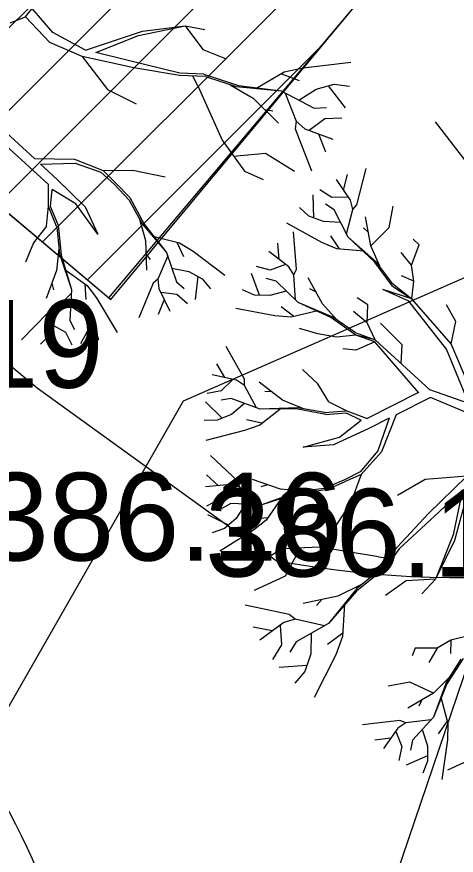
# Model space of a CAD drawing. Extents: x -438233 to -437334, y -1133133 to -1132623.
# Drawn here: x -438141.5 to -438137.75, y -1132967.72 to -1132960.55 of the extents above; entities that cross this region are included whole.
import ezdxf

# ---------------------------------------------------------------- set-up
doc = ezdxf.new("R2010")
doc.units = 0
for name, color, linetype in [('Vrstva 1', 7, 'Continuous'), ('Vrstva 11', 7, 'Continuous'), ('Vrstva 3', 7, 'Continuous'), ('Vrstva 40', 7, 'Continuous'), ('Vrstva 53', 7, 'Continuous')]:
    doc.layers.add(name, color=color, linetype=linetype)

msp = doc.modelspace()

# ---------------------------------------------------------------- linework, layer by layer
at = {"layer": 'Vrstva 1'}
for p, q in [((-438141.4293, -1132960.546), (-438141.3741, -1132960.4752)), ((-438141.1972, -1132960.6792), (-438141.3741, -1132960.4752)), ((-438141.5613, -1132960.5982), (-438141.4293, -1132960.546)), ((-438141.2218, -1132960.7661), (-438141.4293, -1132960.546)), ((-438140.4655, -1132960.7055), (-438140.0649, -1132960.6234)), ((-438140.4295, -1132960.669), (-438140.0649, -1132960.6234)), ((-438140.0649, -1132960.6234), (-438139.9149, -1132960.8255)), ((-438140.0649, -1132960.6234), (-438139.8963, -1132960.654)), ((-438140.9165, -1132960.8303), (-438141.1972, -1132960.6792)), ((-438140.9165, -1132960.8303), (-438140.4295, -1132960.669)), ((-438140.8302, -1132960.8519), (-438140.4655, -1132960.7055)), ((-438140.9459, -1132960.8855), (-438141.2218, -1132960.7661)), ((-438140.5633, -1132960.9167), (-438140.8302, -1132960.8519)), ((-438139.9149, -1132960.8255), (-438139.7146, -1132960.9059)), ((-438140.9459, -1132960.8855), (-438140.7282, -1132961.1668)), ((-438140.5033, -1132960.9832), (-438140.9459, -1132960.8855)), ((-438140.1122, -1132961.0264), (-438140.5633, -1132960.9167)), ((-438139.0567, -1132960.9814), (-438138.65, -1132960.9335)), ((-438140.1134, -1132961.0474), (-438140.5033, -1132960.9832)), ((-438139.9065, -1132961.0354), (-438140.1122, -1132961.0264)), ((-438139.4615, -1132961.1584), (-438139.2186, -1132961.0174)), ((-438139.2186, -1132961.0174), (-438139.0567, -1132960.9814)), ((-438139.8927, -1132961.057), (-438140.1134, -1132961.0474)), ((-438139.9575, -1132961.1368), (-438140.0001, -1132961.0522)), ((-438139.9065, -1132961.0354), (-438139.6102, -1132961.132)), ((-438139.8927, -1132961.057), (-438139.63, -1132961.1428)), ((-438139.2438, -1132961.0318), (-438139.0909, -1132961.0894)), ((-438140.7282, -1132961.1668), (-438140.4829, -1132961.2885)), ((-438139.9575, -1132961.1368), (-438139.7506, -1132961.6016)), ((-438139.6798, -1132961.1266), (-438139.4855, -1132961.2411)), ((-438139.63, -1132961.1428), (-438139.2444, -1132961.18)), ((-438139.6102, -1132961.132), (-438139.2444, -1132961.18)), ((-438139.0939, -1132961.2573), (-438138.9451, -1132961.1638)), ((-438138.9451, -1132961.1638), (-438138.7928, -1132961.1224)), ((-438138.845, -1132961.1368), (-438138.6998, -1132961.3251)), ((-438138.7928, -1132961.1224), (-438138.662, -1132961.1386)), ((-438139.4855, -1132961.2411), (-438139.2684, -1132961.4546)), ((-438139.2444, -1132961.18), (-438138.9631, -1132961.3257)), ((-438139.2108, -1132961.1974), (-438139.1184, -1132961.4391)), ((-438139.3859, -1132961.3389), (-438139.3164, -1132961.3503)), ((-438138.9631, -1132961.3257), (-438138.8593, -1132961.3221)), ((-438139.1184, -1132961.4391), (-438139.1262, -1132961.5044)), ((-438139.1184, -1132961.4391), (-438139.0441, -1132961.5038)), ((-438139.0057, -1132961.5158), (-438138.8725, -1132961.4157)), ((-438138.8725, -1132961.4157), (-438138.7262, -1132961.4097)), ((-438137.6767, -1132961.7678), (-438137.928, -1132961.444)), ((-438139.1262, -1132961.5044), (-438138.9847, -1132961.8619)), ((-438139.0441, -1132961.5038), (-438138.8036, -1132961.592)), ((-438141.5925, -1132961.5374), (-438141.3525, -1132961.7587)), ((-438138.9271, -1132961.547), (-438138.8659, -1132961.7)), ((-438141.5961, -1132961.6484), (-438141.2326, -1132961.9794)), ((-438139.7506, -1132961.6016), (-438139.5599, -1132961.8655)), ((-438139.6528, -1132961.7371), (-438139.3805, -1132961.7125)), ((-438139.3805, -1132961.7125), (-438139.1316, -1132961.8667)), ((-438141.3525, -1132961.7587), (-438141.0101, -1132961.7635)), ((-438141.3028, -1132961.8049), (-438141.0059, -1132961.7977)), ((-438141.3028, -1132961.8049), (-438141.1588, -1132961.9375)), ((-438141.0101, -1132961.7635), (-438140.7672, -1132961.8595)), ((-438141.0059, -1132961.7977), (-438140.7858, -1132961.8745)), ((-438140.7858, -1132961.8745), (-438140.67, -1132961.9794)), ((-438140.7672, -1132961.8595), (-438140.5129, -1132961.8565)), ((-438140.7672, -1132961.8595), (-438140.6574, -1132961.9674)), ((-438140.5129, -1132961.8565), (-438140.237, -1132961.9153)), ((-438139.5599, -1132961.8655), (-438139.3985, -1132961.9363)), ((-438138.5974, -1132962.1535), (-438138.52, -1132961.8428)), ((-438141.1588, -1132961.9375), (-438140.9213, -1132962.1708)), ((-438138.6531, -1132962.1145), (-438138.7737, -1132961.9382)), ((-438138.7113, -1132962.0287), (-438138.6789, -1132961.895)), ((-438141.232, -1132962.1642), (-438141.2326, -1132961.9794)), ((-438141.2152, -1132962.1666), (-438141.2032, -1132962.0238)), ((-438141.0011, -1132962.1444), (-438141.2032, -1132962.0238)), ((-438140.5429, -1132962.1126), (-438140.67, -1132961.9794)), ((-438140.6574, -1132961.9674), (-438140.5387, -1132962.0916)), ((-438138.8121, -1132962.0911), (-438138.9146, -1132962.0245)), ((-438140.5387, -1132962.0916), (-438140.4163, -1132962.3201)), ((-438138.965, -1132962.2668), (-438138.9728, -1132962.0689)), ((-438138.6735, -1132962.0875), (-438138.8121, -1132962.0911)), ((-438141.2494, -1132962.3357), (-438141.232, -1132962.1642)), ((-438141.163, -1132962.3435), (-438141.2314, -1132962.1732)), ((-438141.1516, -1132962.3261), (-438141.2152, -1132962.1666)), ((-438140.811, -1132962.4035), (-438141.0011, -1132962.1444)), ((-438140.9213, -1132962.1708), (-438140.811, -1132962.4035)), ((-438140.5429, -1132962.1126), (-438140.4343, -1132962.3153)), ((-438138.7935, -1132962.1955), (-438138.866, -1132962.1481)), ((-438138.6339, -1132962.1943), (-438138.6531, -1132962.1145)), ((-438138.6339, -1132962.1943), (-438138.5974, -1132962.1535)), ((-438138.3227, -1132962.3484), (-438138.2879, -1132962.1649)), ((-438139.0076, -1132962.2513), (-438139.0886, -1132962.1769)), ((-438138.6735, -1132962.4306), (-438138.7935, -1132962.1955)), ((-438138.6879, -1132962.4024), (-438138.6339, -1132962.1943)), ((-438140.4547, -1132962.2769), (-438140.4043, -1132962.4586)), ((-438140.4343, -1132962.3153), (-438140.2238, -1132962.5606)), ((-438138.8972, -1132962.475), (-438139.1959, -1132962.3106)), ((-438138.884, -1132962.2968), (-438139.0076, -1132962.2513)), ((-438138.7383, -1132962.3052), (-438138.884, -1132962.2968)), ((-438138.4798, -1132962.5055), (-438138.5236, -1132962.256)), ((-438141.2494, -1132962.3357), (-438141.3609, -1132962.4784)), ((-438141.163, -1132962.3435), (-438141.139, -1132962.5726)), ((-438141.1516, -1132962.3261), (-438141.124, -1132962.5846)), ((-438140.4163, -1132962.3201), (-438140.2238, -1132962.5606)), ((-438139.1155, -1132962.7029), (-438139.1401, -1132962.3838)), ((-438138.5002, -1132962.3916), (-438138.5422, -1132962.3502)), ((-438138.4798, -1132962.5055), (-438138.3227, -1132962.3484)), ((-438140.4043, -1132962.4586), (-438140.3971, -1132962.7123)), ((-438140.3426, -1132962.4227), (-438140.1146, -1132962.4778)), ((-438138.7455, -1132962.5313), (-438138.8211, -1132962.418)), ((-438138.448, -1132962.6399), (-438138.6735, -1132962.4306)), ((-438138.4294, -1132962.6429), (-438138.6735, -1132962.4306)), ((-438138.0648, -1132962.4948), (-438138.1181, -1132962.448)), ((-438141.3609, -1132962.4784), (-438141.4311, -1132962.6452)), ((-438141.1438, -1132962.5294), (-438141.1648, -1132962.7165)), ((-438140.138, -1132962.4718), (-438140.0793, -1132962.5954)), ((-438140.1146, -1132962.4778), (-438139.9965, -1132962.5498)), ((-438139.2637, -1132962.6207), (-438139.2751, -1132962.4828)), ((-438138.7695, -1132962.5289), (-438138.8972, -1132962.475)), ((-438138.5362, -1132962.5499), (-438138.7695, -1132962.5289)), ((-438138.4036, -1132962.6771), (-438138.4798, -1132962.5055)), ((-438138.1313, -1132962.6705), (-438138.0648, -1132962.4948)), ((-438141.139, -1132962.5726), (-438141.0359, -1132962.8791)), ((-438141.124, -1132962.5846), (-438141.0359, -1132962.8791)), ((-438140.4007, -1132962.5744), (-438140.3653, -1132962.6218)), ((-438140.2136, -1132962.5906), (-438140.2982, -1132962.7891)), ((-438140.2238, -1132962.5606), (-438140.1392, -1132962.8113)), ((-438139.9965, -1132962.5498), (-438139.7254, -1132962.7561)), ((-438139.1809, -1132962.6831), (-438139.3507, -1132962.5541)), ((-438138.1313, -1132962.6705), (-438138.2213, -1132962.5607)), ((-438139.2079, -1132962.6645), (-438139.3387, -1132962.7113)), ((-438138.2939, -1132962.8492), (-438138.448, -1132962.6399)), ((-438138.2927, -1132962.8276), (-438138.4294, -1132962.6429)), ((-438138.111, -1132962.806), (-438138.1313, -1132962.6705)), ((-438141.1648, -1132962.7165), (-438141.253, -1132962.954)), ((-438141.0941, -1132962.7063), (-438140.9033, -1132962.8431)), ((-438140.1788, -1132962.695), (-438140.0349, -1132962.7237)), ((-438140.0349, -1132962.7237), (-438139.9203, -1132962.7867)), ((-438139.4292, -1132962.9272), (-438139.4988, -1132962.7419)), ((-438139.3387, -1132962.7113), (-438139.4568, -1132962.6807)), ((-438139.1371, -1132962.7532), (-438139.1809, -1132962.6831)), ((-438139.1371, -1132962.7532), (-438139.1155, -1132962.7029)), ((-438140.2982, -1132962.7891), (-438140.3402, -1132962.8239)), ((-438140.2982, -1132962.7891), (-438140.291, -1132962.8707)), ((-438140.1392, -1132962.8113), (-438140.0751, -1132962.8689)), ((-438139.9587, -1132962.7657), (-438139.9803, -1132962.963)), ((-438139.9203, -1132962.7867), (-438139.8502, -1132962.8725)), ((-438139.2889, -1132962.8054), (-438139.3722, -1132962.7826)), ((-438139.1, -1132962.9902), (-438139.2889, -1132962.8054)), ((-438139.1227, -1132962.9686), (-438139.1371, -1132962.7532)), ((-438138.893, -1132963.001), (-438139.0136, -1132962.7772)), ((-438138.111, -1132962.806), (-438138.2165, -1132962.761)), ((-438138.1283, -1132962.9578), (-438138.111, -1132962.806)), ((-438141.205, -1132962.8251), (-438141.1894, -1132962.8821)), ((-438141.0359, -1132962.8791), (-438141.0509, -1132963.1424)), ((-438140.9231, -1132962.8293), (-438140.9147, -1132962.9648)), ((-438140.9033, -1132962.8431), (-438140.8206, -1132962.954)), ((-438140.3402, -1132962.8239), (-438140.4613, -1132963.1202)), ((-438140.291, -1132962.8707), (-438140.1974, -1132963.0626)), ((-438139.4736, -1132962.9254), (-438139.5744, -1132962.8804)), ((-438139.2019, -1132962.8912), (-438139.3429, -1132962.9302)), ((-438138.9482, -1132962.8984), (-438139.0016, -1132962.872)), ((-438138.1547, -1132962.977), (-438138.3754, -1132962.8792)), ((-438138.1283, -1132962.9578), (-438138.3754, -1132962.8792)), ((-438138.2939, -1132962.8492), (-438138.1283, -1132962.9578)), ((-438138.2927, -1132962.8276), (-438138.2927, -1132962.8276)), ((-438138.2927, -1132962.8276), (-438138.1283, -1132962.9578)), ((-438141.0371, -1132962.9103), (-438141.1894, -1132963.0626)), ((-438140.8206, -1132962.954), (-438140.646, -1132963.2467)), ((-438140.2742, -1132962.9007), (-438140.1362, -1132962.9175)), ((-438140.1362, -1132962.9175), (-438140.0451, -1132962.9978)), ((-438139.3429, -1132962.9302), (-438139.4736, -1132962.9254)), ((-438138.5056, -1132963.0081), (-438138.595, -1132962.9488)), ((-438137.7937, -1132963.3422), (-438138.1283, -1132962.9578)), ((-438141.0437, -1132963.02), (-438140.9213, -1132963.101)), ((-438140.2448, -1132962.9642), (-438140.297, -1132963.0926)), ((-438139.1371, -1132963.1083), (-438139.2451, -1132963.0249)), ((-438138.8205, -1132963.1185), (-438139.1, -1132962.9902)), ((-438138.8025, -1132963.1149), (-438139.1, -1132962.9902)), ((-438138.7665, -1132963.1395), (-438138.893, -1132963.001)), ((-438138.5116, -1132963.1641), (-438138.5056, -1132963.0081)), ((-438137.8315, -1132963.389), (-438138.1547, -1132962.977)), ((-438137.7535, -1132963.1521), (-438137.8327, -1132963.0099)), ((-438141.2422, -1132963.08), (-438141.4653, -1132963.3085)), ((-438141.1894, -1132963.0626), (-438141.2422, -1132963.08)), ((-438141.1894, -1132963.0626), (-438141.214, -1132963.1412)), ((-438140.9213, -1132963.101), (-438140.8386, -1132963.2023)), ((-438139.2991, -1132963.1029), (-438139.6337, -1132963.0411)), ((-438139.1605, -1132963.1137), (-438139.2991, -1132963.1029)), ((-438138.9326, -1132963.0609), (-438139.1605, -1132963.1137)), ((-438138.5116, -1132963.1641), (-438138.6267, -1132963.0675)), ((-438141.214, -1132963.1412), (-438141.199, -1132963.3541)), ((-438141.2098, -1132963.1748), (-438141.0881, -1132963.2419)), ((-438141.0509, -1132963.1424), (-438141.0125, -1132963.2203)), ((-438140.8667, -1132963.1682), (-438140.9603, -1132963.3427)), ((-438138.6082, -1132963.2672), (-438138.8205, -1132963.1185)), ((-438138.6135, -1132963.2469), (-438138.8025, -1132963.1149)), ((-438138.4408, -1132963.3086), (-438138.5116, -1132963.1641)), ((-438138.2123, -1132963.3512), (-438138.3976, -1132963.1647)), ((-438137.7937, -1132963.3422), (-438137.7535, -1132963.1521)), ((-438141.2062, -1132963.2455), (-438141.3022, -1132963.3445)), ((-438141.0881, -1132963.2419), (-438141.0335, -1132963.3517)), ((-438140.8386, -1132963.2023), (-438140.8062, -1132963.3079)), ((-438138.9332, -1132963.2564), (-438139.0874, -1132963.2121)), ((-438138.6135, -1132963.2469), (-438138.4408, -1132963.3086)), ((-438138.7737, -1132963.2852), (-438138.9332, -1132963.2564)), ((-438138.6082, -1132963.2672), (-438138.7737, -1132963.2852)), ((-438138.4408, -1132963.3086), (-438138.6082, -1132963.2672)), ((-438138.4462, -1132963.3248), (-438138.6082, -1132963.2672)), ((-438137.9754, -1132963.7351), (-438138.4408, -1132963.3086)), ((-438139.5588, -1132963.6451), (-438139.7141, -1132963.3656)), ((-438138.6082, -1132963.3956), (-438138.7185, -1132963.3848)), ((-438138.4462, -1132963.3248), (-438138.6082, -1132963.3956)), ((-438138.0696, -1132963.7608), (-438138.4462, -1132963.3248)), ((-438138.2201, -1132963.5101), (-438138.2123, -1132963.3512)), ((-438137.6407, -1132963.8532), (-438137.8315, -1132963.389)), ((-438137.567, -1132963.879), (-438137.7937, -1132963.3422)), ((-438139.7273, -1132963.6319), (-438139.7951, -1132963.5125)), ((-438139.6259, -1132963.6547), (-438139.8341, -1132963.6079)), ((-438138.9314, -1132963.6853), (-438139.0622, -1132963.5611)), ((-438139.6595, -1132963.6487), (-438139.7579, -1132963.7459)), ((-438139.5576, -1132963.7003), (-438139.6259, -1132963.6547)), ((-438139.5576, -1132963.7003), (-438139.5588, -1132963.6451)), ((-438139.2325, -1132963.8232), (-438139.4346, -1132963.6703)), ((-438141.329, -1132963.718), (-438141.329, -1132963.718)), ((-438139.7579, -1132963.7459), (-438139.8784, -1132963.7674)), ((-438139.455, -1132963.8898), (-438139.5576, -1132963.7003)), ((-438139.3255, -1132963.753), (-438139.3842, -1132963.7518)), ((-438138.8367, -1132963.8394), (-438138.9314, -1132963.6853)), ((-438137.6407, -1132963.8532), (-438137.9754, -1132963.7351)), ((-438139.6733, -1132963.8106), (-438139.7585, -1132963.825)), ((-438139.425, -1132963.9006), (-438139.6733, -1132963.8106)), ((-438139.0592, -1132963.897), (-438139.2325, -1132963.8232)), ((-438138.0714, -1132963.7596), (-438138.5098, -1132963.9822)), ((-438137.9688, -1132963.8022), (-438138.2615, -1132963.9486)), ((-438137.1022, -1132964.1645), (-438137.9688, -1132963.8022)), ((-438139.7501, -1132963.9798), (-438139.891, -1132963.84)), ((-438139.5582, -1132963.8526), (-438139.6703, -1132963.9462)), ((-438139.2433, -1132963.894), (-438139.4286, -1132964.0373)), ((-438139.1024, -1132963.8892), (-438139.425, -1132963.9006)), ((-438138.8756, -1132963.9306), (-438139.1024, -1132963.8892)), ((-438138.8367, -1132963.8394), (-438138.6837, -1132963.9162)), ((-438139.6703, -1132963.9462), (-438139.7909, -1132963.9966)), ((-438139.1173, -1132963.9), (-438139.425, -1132963.9006)), ((-438138.8625, -1132963.9468), (-438139.1173, -1132963.9)), ((-438138.6909, -1132963.9324), (-438138.5626, -1132963.9942)), ((-438138.6837, -1132963.9162), (-438138.5098, -1132963.9822)), ((-438138.2615, -1132963.9486), (-438138.3868, -1132964.267)), ((-438139.7909, -1132963.9966), (-438139.9018, -1132963.9978)), ((-438139.4286, -1132964.0373), (-438139.5588, -1132964.0853)), ((-438139.4094, -1132964.0223), (-438139.542, -1132963.9918)), ((-438138.7461, -1132964.1405), (-438138.5626, -1132963.9942)), ((-438138.3221, -1132963.9786), (-438138.4966, -1132964.0655)), ((-438138.3221, -1132963.9786), (-438138.4204, -1132964.258)), ((-438139.5588, -1132964.0853), (-438139.8892, -1132964.1687)), ((-438138.4966, -1132964.0655), (-438138.7995, -1132964.2053)), ((-438139.0562, -1132964.2263), (-438138.7461, -1132964.1405)), ((-438138.7995, -1132964.2053), (-438139.0562, -1132964.2263)), ((-438139.6163, -1132964.5177), (-438139.8503, -1132964.2982)), ((-438138.4204, -1132964.258), (-438138.5704, -1132964.4368)), ((-438138.3868, -1132964.267), (-438138.5626, -1132964.4596)), ((-438139.7813, -1132964.5561), (-438139.882, -1132964.4626)), ((-438138.5704, -1132964.4368), (-438138.7095, -1132964.5081)), ((-438138.5626, -1132964.4596), (-438138.7029, -1132964.5243)), ((-438138.5626, -1132964.4596), (-438138.6507, -1132964.6989)), ((-438139.5984, -1132964.5693), (-438139.6163, -1132964.5177)), ((-438139.2511, -1132964.5867), (-438139.491, -1132964.5033)), ((-438138.7095, -1132964.5081), (-438138.8786, -1132964.5795)), ((-438138.8613, -1132964.5915), (-438138.7029, -1132964.5243)), ((-438138.015, -1132964.5033), (-438138.2513, -1132964.6413)), ((-438137.6599, -1132964.4758), (-438138.015, -1132964.5033)), ((-438137.985, -1132964.793), (-438137.6599, -1132964.4758)), ((-438137.6305, -1132964.5309), (-438137.7637, -1132965.0257)), ((-438139.6775, -1132964.5465), (-438139.8904, -1132964.5663)), ((-438139.7111, -1132964.5519), (-438139.7753, -1132964.6743)), ((-438139.5984, -1132964.5693), (-438139.6775, -1132964.5465)), ((-438139.443, -1132964.7181), (-438139.5984, -1132964.5693)), ((-438139.3615, -1132964.5489), (-438139.4178, -1132964.5657)), ((-438139.1066, -1132964.6095), (-438139.4112, -1132964.7193)), ((-438139.064, -1132964.6041), (-438139.2511, -1132964.5867)), ((-438138.8613, -1132964.5915), (-438139.1185, -1132964.6245)), ((-438138.8786, -1132964.5795), (-438139.1066, -1132964.6095)), ((-438137.8962, -1132964.7786), (-438137.6959, -1132964.5921)), ((-438137.6959, -1132964.5921), (-438137.7745, -1132964.9766)), ((-438139.7753, -1132964.6743), (-438139.8832, -1132964.7313)), ((-438139.1185, -1132964.6245), (-438139.4112, -1132964.7193)), ((-438139.2397, -1132964.6575), (-438139.3722, -1132964.8512)), ((-438139.6751, -1132964.7097), (-438139.7525, -1132964.7499)), ((-438139.4112, -1132964.7193), (-438139.6751, -1132964.7097)), ((-438139.5528, -1132964.7145), (-438139.6307, -1132964.838)), ((-438138.6507, -1132964.6989), (-438138.8025, -1132964.9358)), ((-438139.6961, -1132964.8944), (-438139.873, -1132964.8044)), ((-438138.2531, -1132965.0827), (-438137.985, -1132964.793)), ((-438138.2363, -1132965.0953), (-438137.8962, -1132964.7786)), ((-438139.6307, -1132964.838), (-438139.7309, -1132964.9232)), ((-438139.3585, -1132964.8314), (-438139.494, -1132964.8422)), ((-438139.3722, -1132964.8512), (-438139.482, -1132964.9358)), ((-438139.7309, -1132964.9232), (-438139.8347, -1132964.958)), ((-438139.482, -1132964.9358), (-438139.7705, -1132965.1169)), ((-438137.7745, -1132964.9766), (-438137.9256, -1132965.3562)), ((-438137.7637, -1132965.0257), (-438137.9256, -1132965.3562)), ((-438139.2403, -1132965.0953), (-438139.3884, -1132965.1913)), ((-438138.9158, -1132965.0815), (-438139.2403, -1132965.0953)), ((-438139.0826, -1132965.0887), (-438139.2115, -1132965.3286)), ((-438138.4138, -1132965.1643), (-438138.9158, -1132965.0815)), ((-438138.3826, -1132965.2614), (-438138.2531, -1132965.0827)), ((-438138.2363, -1132965.0953), (-438138.3575, -1132965.262)), ((-438138.4138, -1132965.1643), (-438138.3197, -1132965.1751)), ((-438139.289, -1132965.196), (-438139.289, -1132965.196)), ((-438139.2115, -1132965.3286), (-438139.4772, -1132965.4528)), ((-438138.3575, -1132965.262), (-438138.6004, -1132965.457)), ((-438138.3826, -1132965.2614), (-438138.598, -1132965.4342)), ((-438150.6122, -1133004.3095), (-438137.396, -1132965.333)), ((-438138.1769, -1132965.3706), (-438138.3545, -1132965.4942)), ((-438137.9256, -1132965.3562), (-438138.1769, -1132965.3706)), ((-438137.9256, -1132965.3562), (-438138.0444, -1132965.4798)), ((-438138.598, -1132965.4342), (-438138.8409, -1132965.7359)), ((-438138.6004, -1132965.457), (-438138.8409, -1132965.7359)), ((-438138.5578, -1132965.4018), (-438138.7605, -1132965.5007)), ((-438138.7605, -1132965.5007), (-438139.058, -1132965.5649)), ((-438138.8966, -1132965.5295), (-438138.9446, -1132965.5817)), ((-438139.1779, -1132965.6567), (-438139.5534, -1132965.5775)), ((-438138.7047, -1132965.5655), (-438138.7203, -1132965.8462)), ((-438139.1269, -1132965.6987), (-438139.1779, -1132965.6567)), ((-438139.2223, -1132965.7257), (-438139.4286, -1132965.8774)), ((-438139.2535, -1132965.7508), (-438139.2433, -1132965.9164)), ((-438139.1269, -1132965.6987), (-438139.2223, -1132965.7257)), ((-438138.8744, -1132965.7538), (-438139.1269, -1132965.6987)), ((-438138.8409, -1132965.7359), (-438139.1185, -1132965.8906)), ((-438139.3225, -1132965.7988), (-438139.4844, -1132965.7664)), ((-438138.9902, -1132965.8186), (-438138.9926, -1132965.9944)), ((-438138.7179, -1132965.818), (-438138.8505, -1132965.9134)), ((-438139.1185, -1132965.8906), (-438139.1725, -1132965.9794)), ((-438138.7203, -1132965.8462), (-438138.7791, -1132966.0021)), ((-438137.7943, -1132965.878), (-438137.913, -1132965.9446)), ((-438137.7943, -1132965.878), (-438137.7985, -1132965.9926)), ((-438137.6455, -1132965.8402), (-438137.7943, -1132965.878)), ((-438139.2433, -1132965.9164), (-438139.3189, -1132966.0423)), ((-438138.1014, -1132965.9452), (-438138.1259, -1132966.0117)), ((-438137.913, -1132965.9446), (-438138.1014, -1132965.9452)), ((-438137.913, -1132965.9446), (-438137.9838, -1132966.0687)), ((-438138.9926, -1132965.9944), (-438139.0418, -1132966.1443)), ((-438138.7791, -1132966.0021), (-438138.9632, -1132966.3674)), ((-438137.7097, -1132966.0399), (-438137.8339, -1132966.2337)), ((-438137.6893, -1132966.0339), (-438137.8291, -1132966.2516)), ((-438139.025, -1132966.0933), (-438139.2619, -1132966.1107)), ((-438139.0418, -1132966.1443), (-438139.1275, -1132966.2451)), ((-438138.1469, -1132966.2379), (-438138.3305, -1132966.2702)), ((-438137.9442, -1132966.3296), (-438138.1469, -1132966.2379)), ((-438137.8339, -1132966.2337), (-438137.9448, -1132966.5371)), ((-438137.8291, -1132966.2516), (-438137.9448, -1132966.5371)), ((-438137.8105, -1132966.1965), (-438137.9442, -1132966.3296)), ((-438137.9442, -1132966.3296), (-438138.1619, -1132966.4592)), ((-438138.0438, -1132966.3884), (-438138.0678, -1132966.4424)), ((-438137.8824, -1132966.3662), (-438137.8201, -1132966.5911)), ((-438137.9448, -1132966.5371), (-438138.1229, -1132966.7327)), ((-438138.2321, -1132966.5635), (-438138.5494, -1132966.6019)), ((-438138.1805, -1132966.5833), (-438138.2489, -1132966.6295)), ((-438138.1805, -1132966.5833), (-438138.2321, -1132966.5635)), ((-438137.9664, -1132966.5599), (-438138.1805, -1132966.5833)), ((-438137.8261, -1132966.5689), (-438137.9052, -1132966.6793)), ((-438137.8201, -1132966.5911), (-438137.8249, -1132966.7303)), ((-438138.2489, -1132966.6295), (-438138.3706, -1132966.8052)), ((-438138.2669, -1132966.6583), (-438138.2141, -1132966.7866)), ((-438138.0402, -1132966.6415), (-438137.9958, -1132966.7812)), ((-438138.3083, -1132966.7147), (-438138.445, -1132966.7315)), ((-438138.1229, -1132966.7327), (-438138.1415, -1132966.8172)), ((-438137.8249, -1132966.7303), (-438137.8728, -1132967.0679)), ((-438138.2141, -1132966.7866), (-438138.2405, -1132966.906)), ((-438137.9958, -1132966.7812), (-438137.9946, -1132966.9126)), ((-438137.9946, -1132966.8676), (-438138.1775, -1132966.9456)), ((-438137.534, -1132966.8538), (-438137.8243, -1132966.9906)), ((-438137.9946, -1132966.9126), (-438138.036, -1132967.0145))]:
    msp.add_line(p, q, dxfattribs=at)
for points in [[(-438138.8756, -1132963.9306), (-438138.6927, -1132963.9144)], [(-438138.8625, -1132963.9468), (-438138.6909, -1132963.9324)]]:
    msp.add_lwpolyline(points, dxfattribs=at)
msp.add_arc((-438146.86, -1132970.1735), 6, 16.44565, 50.04476, dxfattribs=at)
at = {"layer": 'Vrstva 11'}
msp.add_lwpolyline([(-438153.362, -1132953.683), (-438141.329, -1132963.718), (-438139.289, -1132965.196)], dxfattribs=at)
for centre, radius, start, end in [((-438137.7517, -1132957.101), 8.2397, 259.24714, 296.02808), ((-438145.6136, -1132970.0676), 4.5595, 15.82768, 42.3507)]:
    msp.add_arc(centre, radius, start, end, dxfattribs=at)
at = {"layer": 'Vrstva 40'}
for p, q in [((-438149.0864, -1132955.8955), (-438140.7001, -1132962.9633)), ((-438142.4357, -1132961.5005), (-438139.2519, -1132958.3167)), ((-438142.052, -1132961.8239), (-438138.8682, -1132958.6401)), ((-438141.6683, -1132962.1473), (-438138.4845, -1132958.9635)), ((-438141.2845, -1132962.4707), (-438138.1007, -1132959.2869)), ((-438140.7001, -1132962.9633), (-438137.8335, -1132959.5121)), ((-438140.9008, -1132962.7941), (-438138.9146, -1132960.8079))]:
    msp.add_line(p, q, dxfattribs=at)
msp.add_lwpolyline([(-438149.0864, -1132955.8955), (-438140.7182, -1132962.948), (-438137.8271, -1132959.5175), (-438146.1953, -1132952.465)], close=True, dxfattribs=at)
at = {"layer": 'Vrstva 53'}
msp.add_lwpolyline([(-438111.68, -1133002.95), (-438112.12, -1133002.5), (-438122.55, -1132995.83), (-438124.94, -1132993.34), (-438127.48, -1132990.73), (-438128.12, -1132989.43), (-438134.1, -1132984.54), (-438140.26, -1132979.82), (-438141.19, -1132978.73), (-438141.97, -1132973.72), (-438142.51, -1132968.08), (-438140.08, -1132963.83), (-438137.6, -1132962.74), (-438135.49, -1132962.32), (-438133.71, -1132961.01), (-438132.67, -1132959.55), (-438131.52, -1132960.06), (-438130.71, -1132960.47)], dxfattribs=at)

# ---------------------------------------------------------------- texts
at = {"layer": 'Vrstva 3'}
for s, p in [('386.19 ', (-438143.829, -1132963.718)), ('386.16 ', (-438141.789, -1132965.196)), ('386.16 ', (-438139.896, -1132965.333))]:
    msp.add_text(s, height=0.75, dxfattribs=at).set_placement(p)

doc.saveas('drawing.dxf')
